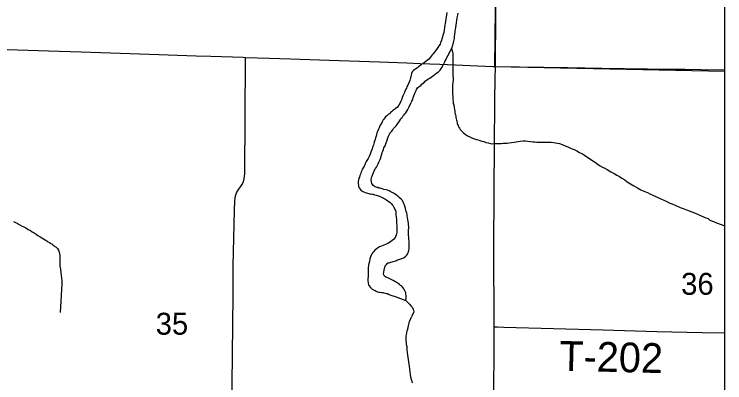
# Model space of a CAD drawing. Extents: x 0 to 68, y 0 to 52.9.
# Drawn here: x 64.407 to 67.997, y 45.541 to 47.401 of the extents above; entities that cross this region are included whole.
import ezdxf

# ---------------------------------------------------------------- set-up
doc = ezdxf.new("R2010")
doc.units = 0
for name, color, linetype in [('Default', 7, 'Continuous'), ('GM_X_Minor_River', 7, 'Continuous'), ('GM_X_Township_Road', 7, 'Continuous'), ('GM_X_Township_Road_Text', 7, 'Continuous')]:
    doc.layers.add(name, color=color, linetype=linetype)

msp = doc.modelspace()

# ---------------------------------------------------------------- linework, layer by layer
at = {"layer": 'Default'}
msp.add_line((67.9972, 34.4614), (67.9972, 52.9414), dxfattribs=at)
for points in [[(67.9972, 47.1124), (66.835, 47.1348), (66.8661, 49.7771), (67.9972, 49.765)], [(66.3482, 46.8538), (66.3534, 46.8608), (66.3585, 46.8687), (66.3626, 46.8757), (66.3677, 46.8797), (66.3708, 46.8857), (66.3759, 46.8906), (66.381, 46.8976), (66.3861, 46.9035), (66.3913, 46.9115), (66.3954, 46.9195), (66.3985, 46.9265), (66.4016, 46.9335), (66.4109, 46.9524), (66.4151, 46.9614), (66.4202, 46.9704), (66.4233, 46.9804), (66.4265, 46.9894), (66.4296, 46.9974), (66.4327, 47.0064), (66.4369, 47.0164), (66.44, 47.0214), (66.4451, 47.0293), (66.4533, 47.0362), (66.4614, 47.0412), (66.4685, 47.0491), (66.4757, 47.055), (66.4838, 47.063), (66.4919, 47.0689), (66.5001, 47.0748), (66.5062, 47.0787), (66.5133, 47.0827), (66.5204, 47.0876), (66.5306, 47.0955), (66.5357, 47.1005), (66.5428, 47.1044), (66.5509, 47.1093), (66.5591, 47.1192), (66.5642, 47.1262), (66.5693, 47.1342), (66.5724, 47.1412), (66.5755, 47.1471), (66.5796, 47.1531), (66.5827, 47.1601), (66.5848, 47.1661), (66.5889, 47.1731), (66.5921, 47.1811), (66.5951, 47.1861), (66.5993, 47.193), (66.6024, 47.201), (66.6075, 47.209), (66.6106, 47.216), (66.6148, 47.225), (66.6189, 47.231), (66.621, 47.239), (66.6231, 47.245), (66.6242, 47.251), (66.6262, 47.256), (66.6284, 47.264), (66.6295, 47.271), (66.6306, 47.279), (66.6317, 47.289), (66.6338, 47.2991), (66.635, 47.3131), (66.6362, 47.3231), (66.6383, 47.3342), (66.6395, 47.3462), (66.6416, 47.3572), (66.6438, 47.3713), (66.645, 47.3833), (66.6481, 47.3953), (66.6493, 47.4063)], [(66.5919, 47.4091), (66.5853, 47.364), (66.5842, 47.355), (66.5831, 47.3459), (66.5809, 47.3329), (66.5797, 47.3209), (66.5776, 47.3088), (66.5744, 47.2978), (66.5712, 47.2858), (66.5681, 47.2758), (66.566, 47.2688), (66.5629, 47.2628), (66.5597, 47.2498), (66.5515, 47.2409), (66.5464, 47.2329), (66.5402, 47.2229), (66.5341, 47.215), (66.5279, 47.207), (66.5228, 47.2001), (66.5187, 47.1951), (66.5136, 47.1891), (66.5085, 47.1822), (66.5013, 47.1742), (66.4952, 47.1693), (66.4861, 47.1624), (66.479, 47.1575), (66.4729, 47.1525), (66.4668, 47.1486), (66.4607, 47.1436), (66.4556, 47.1397), (66.4495, 47.1347), (66.4444, 47.1308), (66.4363, 47.1259), (66.4302, 47.1219), (66.4241, 47.117), (66.4169, 47.1101)], [(66.4169, 47.1101), (66.4138, 47.1021), (66.4127, 47.094), (66.4106, 47.085), (66.4095, 47.079), (66.4074, 47.073), (66.4053, 47.067), (66.3949, 47.043), (66.3908, 47.0351), (66.3887, 47.0281), (66.3856, 47.0221), (66.3825, 47.0151), (66.3794, 47.0061), (66.3742, 46.9961), (66.3711, 46.9881), (66.367, 46.9811), (66.3649, 46.9741), (66.3628, 46.9691), (66.3597, 46.9611), (66.3565, 46.9531), (66.3503, 46.9422), (66.3452, 46.9352), (66.3411, 46.9302), (66.334, 46.9243), (66.3289, 46.9194), (66.3238, 46.9164), (66.3188, 46.9125), (66.3137, 46.9085), (66.3086, 46.9046), (66.3035, 46.8986), (66.2984, 46.8956), (66.2892, 46.8877), (66.2831, 46.8828), (66.279, 46.8778), (66.2739, 46.8719), (66.2718, 46.8669), (66.2657, 46.8579), (66.2636, 46.8529), (66.2595, 46.8459), (66.2564, 46.84), (66.2523, 46.833), (66.2502, 46.827), (66.2471, 46.82), (66.2419, 46.809), (66.2398, 46.802), (66.2377, 46.793), (66.2356, 46.785), (66.2324, 46.777), (66.2303, 46.769), (66.2282, 46.763), (66.2262, 46.758), (66.2251, 46.753), (66.224, 46.746), (66.2219, 46.74), (66.2188, 46.733), (66.2177, 46.728), (66.2156, 46.721), (66.2125, 46.713), (66.2094, 46.704), (66.2052, 46.694), (66.2, 46.683), (66.1949, 46.672), (66.1887, 46.663), (66.1856, 46.6571), (66.1825, 46.6501), (66.1784, 46.6411), (66.1742, 46.6331), (66.1701, 46.6261), (66.167, 46.6201), (66.1639, 46.6131), (66.1608, 46.6072), (66.1587, 46.6002), (66.1556, 46.5932), (66.1535, 46.5862), (66.1514, 46.5792), (66.1483, 46.5732), (66.1462, 46.5642), (66.1451, 46.5561), (66.145, 46.5511), (66.1449, 46.5451), (66.1458, 46.538), (66.1467, 46.531), (66.1497, 46.5239), (66.1546, 46.5178), (66.1576, 46.5128), (66.1636, 46.5097), (66.1686, 46.5066), (66.1736, 46.5045), (66.1806, 46.5014), (66.1977, 46.4962), (66.2027, 46.4951), (66.2077, 46.494), (66.2148, 46.4929), (66.2208, 46.4919), (66.2278, 46.4898), (66.2358, 46.4876), (66.2449, 46.4845), (66.2529, 46.4824), (66.2599, 46.4793), (66.2669, 46.4752), (66.2729, 46.4721)], [(66.3395, 46.1588), (66.3445, 46.1607), (66.3506, 46.1627), (66.3597, 46.1666), (66.3658, 46.1685), (66.3739, 46.1714), (66.3789, 46.1744), (66.384, 46.1783), (66.3891, 46.1833), (66.3932, 46.1892), (66.3963, 46.1952), (66.3994, 46.2012), (66.4015, 46.2092), (66.4026, 46.2172), (66.4027, 46.2253), (66.4028, 46.2333), (66.4029, 46.2403), (66.403, 46.2494), (66.4021, 46.2564), (66.4012, 46.2645), (66.4013, 46.2705), (66.4004, 46.2775), (66.3995, 46.2846), (66.3995, 46.2906), (66.3996, 46.2986), (66.3997, 46.3057), (66.3998, 46.3127), (66.3999, 46.3207), (66.4, 46.3288), (66.3991, 46.3378), (66.3982, 46.3459), (66.3973, 46.3539), (66.3945, 46.374), (66.3926, 46.3821), (66.3917, 46.3902), (66.3898, 46.3962), (66.3879, 46.4053), (66.386, 46.4123), (66.3841, 46.4204), (66.3802, 46.4325), (66.3773, 46.4426), (66.3744, 46.4496), (66.3684, 46.4598), (66.3615, 46.4669), (66.3525, 46.4761), (66.3446, 46.4832), (66.3366, 46.4893), (66.3286, 46.4945), (66.3236, 46.4975), (66.3166, 46.5016), (66.3066, 46.5068), (66.3016, 46.5089), (66.2936, 46.512), (66.2855, 46.5141), (66.2745, 46.5163), (66.2665, 46.5194), (66.2604, 46.5215), (66.2554, 46.5225), (66.2494, 46.5236), (66.2444, 46.5257), (66.2383, 46.5268), (66.2313, 46.5299), (66.2253, 46.533), (66.2203, 46.5371), (66.2134, 46.5472), (66.2115, 46.5543), (66.2106, 46.5663), (66.2128, 46.5773), (66.2149, 46.5833), (66.217, 46.5893), (66.2222, 46.6023), (66.2263, 46.6103), (66.2294, 46.6153), (66.2325, 46.6213), (66.2366, 46.6283), (66.2407, 46.6352), (66.2459, 46.6462), (66.249, 46.6542), (66.2531, 46.6612), (66.2562, 46.6682), (66.2584, 46.6762), (66.2605, 46.6852), (66.2636, 46.6952), (66.2658, 46.7032), (66.2689, 46.7102), (66.272, 46.7182), (66.2751, 46.7272), (66.2803, 46.7362), (66.2865, 46.7512), (66.2907, 46.7652), (66.2949, 46.7772), (66.298, 46.7852), (66.3022, 46.7951), (66.3052, 46.8001), (66.3134, 46.8081), (66.3196, 46.817), (66.3237, 46.824), (66.3298, 46.8309), (66.3359, 46.8369), (66.3421, 46.8448), (66.3482, 46.8538)], [(66.2729, 46.4721), (66.2789, 46.469), (66.2839, 46.4649), (66.2899, 46.4618), (66.2949, 46.4587), (66.3059, 46.4506), (66.3128, 46.4444), (66.3168, 46.4394), (66.3208, 46.4343), (66.3257, 46.4262), (66.3286, 46.4181), (66.3326, 46.411), (66.3345, 46.401), (66.3353, 46.3889), (66.3362, 46.3778), (66.338, 46.3647), (66.3379, 46.3537), (66.3388, 46.3436), (66.3397, 46.3366), (66.3406, 46.3316), (66.3405, 46.3205), (66.3404, 46.3125), (66.3403, 46.3044), (66.3402, 46.2984), (66.3381, 46.2924), (66.337, 46.2864), (66.3339, 46.2804), (66.3319, 46.2744), (66.3237, 46.2645), (66.3165, 46.2586), (66.3074, 46.2516), (66.2942, 46.2428), (66.2831, 46.2379), (66.2577, 46.2282), (66.2517, 46.2263), (66.2466, 46.2233), (66.2415, 46.2194), (66.2354, 46.2144), (66.2293, 46.2095), (66.2242, 46.2035), (66.2181, 46.1976), (66.213, 46.1916), (66.2099, 46.1846), (66.2067, 46.1756), (66.2036, 46.1656), (66.2014, 46.1536), (66.1983, 46.1426), (66.1971, 46.1336), (66.196, 46.1215), (66.1948, 46.1095), (66.1947, 46.0984), (66.1945, 46.0854), (66.1944, 46.0753), (66.1943, 46.0663), (66.1941, 46.0563), (66.195, 46.0442), (66.1969, 46.0361), (66.1989, 46.0311), (66.2068, 46.0209), (66.2158, 46.0138), (66.2248, 46.0076), (66.2298, 46.0056), (66.2348, 46.0025), (66.2428, 46.0004), (66.2488, 45.9983), (66.2548, 45.9972), (66.2629, 45.9971), (66.2689, 45.996), (66.275, 45.9949), (66.281, 45.9928), (66.288, 45.9917), (66.293, 45.9907), (66.302, 45.9865), (66.309, 45.9834), (66.3141, 45.9813), (66.3191, 45.9793), (66.3261, 45.9772), (66.3311, 45.9761), (66.3862, 45.9553)], [(66.3862, 45.9553), (66.3874, 45.9673), (66.3866, 45.9814), (66.3856, 45.9874), (66.3847, 45.9945), (66.3808, 46.0046), (66.3759, 46.0147), (66.37, 46.0218), (66.365, 46.0289), (66.359, 46.032), (66.354, 46.0361), (66.3471, 46.0422), (66.3421, 46.0453), (66.3371, 46.0493), (66.3301, 46.0525), (66.321, 46.0566), (66.3151, 46.0607), (66.308, 46.0638), (66.302, 46.0669), (66.294, 46.07), (66.285, 46.0741), (66.278, 46.0793), (66.2731, 46.0884), (66.2743, 46.0994), (66.2754, 46.1084), (66.2817, 46.1314), (66.2878, 46.1384), (66.295, 46.1453), (66.302, 46.1462), (66.3101, 46.1491), (66.3162, 46.1511), (66.3223, 46.153), (66.3283, 46.1549), (66.3344, 46.1569), (66.3395, 46.1588)], [(66.3862, 45.9553), (66.3982, 45.9421), (66.4042, 45.938), (66.4131, 45.9278), (66.417, 45.9217), (66.42, 45.9167), (66.422, 45.9116), (66.4239, 45.9056), (66.4258, 45.8995), (66.4137, 45.8739)], [(66.3969, 45.8189), (66.3979, 45.8239), (66.3989, 45.8289), (66.4009, 45.835), (66.402, 45.841), (66.403, 45.847), (66.406, 45.854), (66.4137, 45.8739)], [(66.4213, 45.5399), (66.4173, 45.546), (66.4153, 45.553), (66.4123, 45.562), (66.4104, 45.5711), (66.4094, 45.5831), (66.4074, 45.5962), (66.4054, 45.6102), (66.4045, 45.6253), (66.3956, 45.6795), (66.3936, 45.6935), (66.3926, 45.7076), (66.3916, 45.7216), (66.3897, 45.7347), (66.3887, 45.7447), (66.3867, 45.7527), (66.3867, 45.7598), (66.3877, 45.7668), (66.3878, 45.7758), (66.3888, 45.7828), (66.3898, 45.7929), (66.3918, 45.8029), (66.3949, 45.8119), (66.3969, 45.8189)]]:
    msp.add_lwpolyline(points, dxfattribs=at)
at = {"layer": 'GM_X_Minor_River'}
for points in [[(66.6168, 47.2279), (66.6216, 47.2108), (66.6225, 47.2008), (66.6224, 47.1937), (66.6224, 47.1877), (66.6223, 47.1797), (66.6232, 47.1726), (66.623, 47.1596), (66.6229, 47.1475), (66.6237, 47.1345), (66.6235, 47.1204), (66.6234, 47.1073), (66.6232, 47.0923), (66.624, 47.0792), (66.6239, 47.0682), (66.6227, 47.0561), (66.6216, 47.0451), (66.6214, 47.033), (66.6213, 47.02), (66.6211, 47.0039), (66.6228, 46.9788), (66.6254, 46.9516), (66.6273, 46.9415), (66.6292, 46.9305), (66.6311, 46.9204), (66.633, 46.9123), (66.6339, 46.9053), (66.6348, 46.8982), (66.6368, 46.8932), (66.6377, 46.8862), (66.6386, 46.8791), (66.6405, 46.8721), (66.6415, 46.866), (66.6434, 46.861), (66.6444, 46.8549), (66.6453, 46.8499), (66.6472, 46.8448), (66.6502, 46.8388), (66.6521, 46.8327), (66.6561, 46.8256), (66.66, 46.8196), (66.668, 46.8104), (66.6739, 46.8053), (66.6789, 46.8002), (66.6849, 46.7961), (66.6909, 46.792), (66.6979, 46.7869), (66.7059, 46.7828), (66.7149, 46.7787), (66.7219, 46.7746), (66.7329, 46.7724), (66.742, 46.7693), (66.751, 46.7661), (66.76, 46.764), (66.7691, 46.7609), (66.7801, 46.7577), (66.7901, 46.7536), (66.8012, 46.7514), (66.8132, 46.7482), (66.8243, 46.7471), (66.8344, 46.748), (66.8485, 46.7478), (66.8585, 46.7486), (66.8686, 46.7485), (66.8777, 46.7494), (66.8868, 46.7503), (66.8968, 46.7501), (66.9079, 46.752), (66.92, 46.7539), (66.9321, 46.7547), (66.9634, 46.7603), (66.9786, 46.7611), (66.9906, 46.761), (67.0027, 46.7598), (67.0158, 46.7586), (67.0279, 46.7575), (67.0379, 46.7563), (67.047, 46.7552), (67.058, 46.7551), (67.0711, 46.7549), (67.0873, 46.7557), (67.1034, 46.7555), (67.1205, 46.7552), (67.1315, 46.7541), (67.1416, 46.752), (67.1516, 46.7498), (67.1617, 46.7477), (67.1747, 46.7435), (67.1898, 46.7373), (67.2048, 46.731), (67.2208, 46.7238), (67.2358, 46.7176), (67.2488, 46.7114), (67.2628, 46.7031), (67.2779, 46.6969), (67.2889, 46.6897), (67.3008, 46.6816), (67.3128, 46.6724), (67.3258, 46.6641), (67.3388, 46.6559), (67.3508, 46.6477)], [(67.3508, 46.6477), (67.3647, 46.6375), (67.3787, 46.6293), (67.3907, 46.6231), (67.4028, 46.6169), (67.4217, 46.6056), (67.4377, 46.5964), (67.4517, 46.5882), (67.4647, 46.581), (67.4777, 46.5727), (67.4917, 46.5645), (67.5047, 46.5553), (67.5207, 46.5451), (67.5377, 46.5348), (67.5557, 46.5245), (67.5727, 46.5152), (67.5887, 46.507), (67.6067, 46.5007), (67.6187, 46.4945), (67.6328, 46.4883), (67.6738, 46.4687), (67.6899, 46.4625), (67.7039, 46.4563), (67.7189, 46.448), (67.7349, 46.4418), (67.7499, 46.4346), (67.771, 46.4252), (67.787, 46.42), (67.803, 46.4138), (67.8171, 46.4086), (67.8301, 46.4034), (67.8441, 46.3982), (67.8592, 46.3919), (67.8752, 46.3847), (67.8902, 46.3785), (67.9022, 46.3733), (67.9133, 46.3691), (67.9222, 46.362), (67.9403, 46.3547), (67.9553, 46.3475), (67.9972, 46.3329)], [(64.4031, 46.3551), (64.4131, 46.3499), (64.4211, 46.3458), (64.4311, 46.3397), (64.4431, 46.3325), (64.4551, 46.3273), (64.4651, 46.3221), (64.4771, 46.3149), (64.4881, 46.3088), (64.4981, 46.3026), (64.5071, 46.2975), (64.5171, 46.2913), (64.5261, 46.2842), (64.5371, 46.278), (64.5461, 46.2728), (64.5541, 46.2667), (64.5631, 46.2616), (64.5711, 46.2574), (64.5771, 46.2523), (64.5841, 46.2492), (64.5911, 46.2441), (64.5961, 46.2411), (64.601, 46.237), (64.606, 46.2329), (64.612, 46.2288), (64.618, 46.2247), (64.626, 46.2176), (64.6309, 46.2105), (64.6319, 46.2054), (64.6338, 46.1994), (64.6347, 46.1923), (64.6366, 46.1833), (64.6375, 46.1742), (64.6374, 46.1642), (64.6379, 46.129), (64.6398, 46.1149), (64.6416, 46.0958), (64.6444, 46.0827), (64.6452, 46.0686), (64.6471, 46.0545), (64.6479, 46.0395), (64.638, 45.8949)]]:
    msp.add_lwpolyline(points, dxfattribs=at)
at = {"layer": 'GM_X_Township_Road'}
for points in [[(66.8378, 47.1374), (66.8384, 47.1639), (66.84, 47.3774), (66.8451, 47.796), (66.8484, 48.0505), (66.8501, 48.1901), (66.8539, 48.5184), (66.8581, 48.8303), (66.8597, 48.9945), (66.8627, 49.4132), (66.8628, 49.6102), (66.8647, 49.7803)], [(64.0553, 47.233), (64.5801, 47.2162), (64.7441, 47.2112), (64.9901, 47.203), (65.1378, 47.198), (65.3263, 47.1909), (65.4002, 47.1889), (65.5641, 47.1832), (65.5755, 47.1828)], [(65.4928, 44.5488), (65.4941, 44.5632), (65.4952, 44.6124), (65.5056, 45.3841), (65.5134, 45.9834), (65.5135, 46.1312), (65.5192, 46.4103), (65.5206, 46.4596), (65.5246, 46.4838), (65.5301, 46.4992), (65.538, 46.5135), (65.5569, 46.5405), (65.5644, 46.555), (65.5691, 46.5706), (65.5721, 46.595), (65.5754, 47.1697), (65.5755, 47.1828)], [(65.5755, 47.1828), (65.6954, 47.1789), (65.802, 47.1749), (65.9988, 47.1695), (66.253, 47.1605), (66.3901, 47.1552), (66.4565, 47.1521), (66.5566, 47.1486), (66.8268, 47.1377), (66.8378, 47.1374)], [(66.8317, 45.8235), (66.8319, 45.9416), (66.8305, 46.1139), (66.8296, 46.2042), (66.8302, 46.311), (66.832, 46.4176), (66.8316, 46.5241), (66.8335, 46.7289), (66.8356, 46.967), (66.8364, 47.0737), (66.8378, 47.1374)], [(66.8378, 47.1374), (67.2043, 47.1317), (67.3765, 47.1284), (67.7211, 47.1238), (67.795, 47.123), (67.877, 47.1212), (67.9972, 47.1194)], [(67.0509, 44.4971), (66.9891, 44.6065), (66.9442, 44.6848), (66.89, 44.7767), (66.8468, 44.8465), (66.8352, 44.8683), (66.829, 44.8835), (66.8265, 44.8913), (66.8245, 44.8992), (66.8231, 44.9073), (66.8221, 44.9237), (66.8275, 45.252), (66.8282, 45.3998), (66.8305, 45.5065), (66.8314, 45.6953), (66.8317, 45.8235)], [(66.8317, 45.8235), (66.8483, 45.8227), (66.8811, 45.821), (67.3821, 45.8074), (67.6532, 45.8), (67.8832, 45.7948), (67.9972, 45.7927)]]:
    msp.add_lwpolyline(points, dxfattribs=at)

# ---------------------------------------------------------------- texts
at = {"layer": 'Default'}
for s, p in [('36', (67.7767, 45.9848)), ('35', (65.1215, 45.7835))]:
    msp.add_text(s, height=0.1105, rotation=0, dxfattribs=at).set_placement(p)
at = {"layer": 'GM_X_Township_Road_Text'}
msp.add_text('T-202', height=0.15, rotation=358.5957, dxfattribs=at).set_placement((67.1594, 45.6022))

doc.saveas('drawing.dxf')
